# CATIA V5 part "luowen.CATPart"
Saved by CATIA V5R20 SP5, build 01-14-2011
Part number: 瓶口螺纹
Bounding box of the stored display mesh (mm): x -16.165 to 16.166, y -16.164 to 16.156, z 0 to 20
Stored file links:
  E:\画图\luowen.CATPart
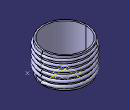
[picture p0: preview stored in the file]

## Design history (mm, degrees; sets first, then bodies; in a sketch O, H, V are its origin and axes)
Body1 (main body)
  Sketch1 on xy-plane, origin (0, 0, 0), H (1, 0, 0), V (0, 1, 0)
    circle A1 centre (0, 0) radius 15
    radius A1 = 15
  Pad1: profile Sketch1, direction (0, 0, 1), length 20, thin wall 1
  Plane1: type Offset, RefPlane xy-plane, Offset 2
  Sketch2 on Plane1, origin (0, 0, 2), H (1, 0, 0), V (0, 1, 0)
    point P1 (0, 0)
    point P2 (15, 0)
    distance P2 P1 = 15
    coincidence: P1 O, P2 H
  Helix1: Direction Z axis, RefPoint Sketch2.P2, Pitch 3, Height 16, TaperAngle 0
  Sketch3 on Plane1, origin (0, 0, 2), H (1, 0, 0), V (0, 1, 0)
    point P1 (15, -10)
    point P2 (5, -10)
    distance P1 V = 15
    distance P1 H = 10
    distance P2 P1 = 10
  Line1: type PtPt, FirstPoint Sketch2.P2, SecondPoint Sketch3.P1
  Line2: type PtPt, FirstPoint Sketch3.P1, SecondPoint Sketch3.P2
  Line3: type Tangency, RefPoint vertex of Helix1, Curve Helix1, Start 0, End 10
  Plane2: type Normal, Curve Helix1, RefPoint Sketch3.P2
  Sketch4 on Plane2, origin (0.1275, 0.0626, 0.0045), H (-0.4409, 0.8975, 0), V (-0.0286, -0.014, 0.9995)
    circle A1 centre (-11.1913, 2.0035) radius 1
    radius A1 = 1
  Connect1: Curve1 Line2, Point1 Sketch3.P2, Tension1 1, Curve2 Line1, Point2 Sketch2.P2, Tension2 1
  Point1: (10, -10, 0), relative to vertex of Line3
  Line4: type PtPt, FirstPoint Point1, SecondPoint vertex of Line3
  Connect2: Curve1 Line4, Point1 Point1, Tension1 1, Curve2 Line3, Point2 vertex of Helix1, Tension2 0.1
  Plane3: type Normal, Curve Helix1, RefPoint vertex of Helix1
  Sketch5 on Plane3, origin (-0.4957, -0.2862, 0.0182), H (0.5, -0.866, 0), V (0.0276, 0.0159, 0.9995)
    circle A1 centre (-15.1225, 18.1029) radius 1
    radius A1 = 1
  Rib1: profile Sketch5, centre curve Helix1
  Plane4: type Normal, Curve Connect2, RefPoint Point1
  Sketch6 on Plane4, origin (-2.0744, 2.0744, 0), H (-0.7071, -0.7071, 0), V (0, 0, 1)
    circle A1 centre (5.8851, 18.5857) radius 1
    radius A1 = 1
  Rib2: profile Sketch4, centre curve Connect1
